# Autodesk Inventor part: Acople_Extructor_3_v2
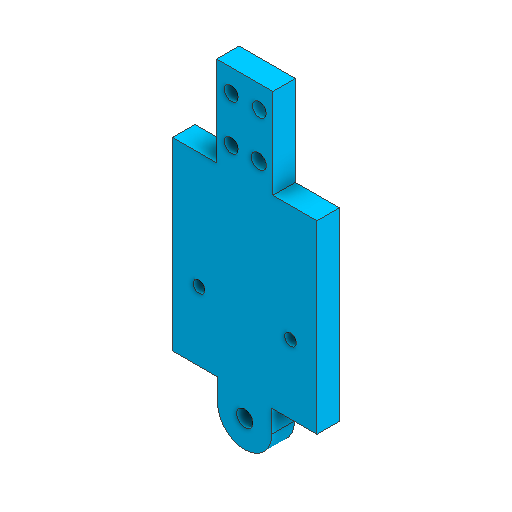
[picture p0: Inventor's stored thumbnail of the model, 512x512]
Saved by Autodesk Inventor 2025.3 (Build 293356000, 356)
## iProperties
Created: 2025-11
Part Number: Acople_Extructor_3_v2
Material: Plástico SAN
Document SubType Name: Modeling
Designer: Dell
Density: 1.068 g/cm^3
Appearance: Valor por defecto
Mass: 69.8287 g
Surface Area: 184.87 cm^2
Volume: 65.3827 cm^3
Author: Dell
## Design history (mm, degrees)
sketch "Boceto1"
  geometry: L1 (-12.5, 0)-(-12.5, -40); L2 (12.5, 0)-(12.5, -40); L3 (12.5, -40)-(-12.5, -40); L4 (-12.5, 0)-(12.5, 0); C1 r 3.1 at (6.5, -10); C2 r 3.1 at (-6, -10); C3 r 3.1 at (6.5, -30); C4 r 3.1 at (-6, -30); 1 further point
  constraints: 8 end point, 4 centre point, 2 vertical, 1 horizontal, 1 perpendicular
  dimensions: "d0" = 25 distance of L1.start L2.start; "d1" = 40 distance of L1.start L1.end; "d4" = 6.2 diameter of C1; "d6" = 6.2 diameter of C2; "d8" = 6.2 diameter of C3; "d9" = 6.2 diameter of C4
node "Plano de trabajo1"
sketch "Boceto2"
  geometry: L1 (-19.6, 0)-(44.6, 0); L2 (-19.6, 0)-(-19.6, 10); L3 (-19.6, 10)-(44.6, 10); L4 (44.6, 10)-(44.6, 0); 1 further point
  constraints: 8 end point, 2 perpendicular, 1 horizontal, 1 midpoint, 1 vertical
  dimensions: "d20" = 64.2 distance of L1.start L1.end; "d21" = 10 distance of L1.start L2.end
extrude "Extrusión2" join sketch "Boceto2" distance "d22" = 104.2; taper "d23" = 0 deg
node "Plano de trabajo2"
sketch "Boceto3" dims "d98" = 5.5
  geometry: L1 (12.5, -40)-(32.1, -40) reference; L2 (32.1, -40)-(20.35, -40); L3 (-32.1, -40)-(-12.5, -40) reference; L4 (0, -60)-(0, -132.1); L5 (-32.1, -40)-(-32.1, -144.2) reference; L6 (-32.1, -102.2)-(-32.1, -144.2); L7 (-32.1, -144.2)-(0, -144.2); L8 (32.1, -144.2)-(32.1, -102.2); L9 (32.1, -40)-(32.1, -144.2) reference; L10 (0, -144.2)-(32.1, -144.2); L11 (12.5, -40)-(12.5, 0) reference; L12 (-32.1, -57.5)-(-32.1, -53); L13 (6.441, -122.2)-(32.1, -122.2); L14 (6.441, -122.2)-(-32.1, -122.2); L15 (12.1, -132.1)-(12.1, -122.2); L16 (-12.1, -132.1)-(-12.1, -122.2); L17 (-22.3, -40)-(-22.3, -60); L18 (-22.3, -60)-(32.1, -60); L19 (-21.522, -60)-(-22.3, -60); L20 (-32.1, -60)-(-22.3, -60); L21 (-26, -40)-(-26, -67.5); L22 (-27.6, -67.5)-(-32.1, -67.5); L23 (-20.35, -60)-(-20.35, -91.6); L24 (-20.35, -91.6)-(-32.1, -91.6); L25 (20.35, -91.6)-(20.35, -60); L26 (20.35, -91.6)-(32.1, -91.6); L27 (1.4, -94.7)-(1.4, -60); L28 (1.4, -94.7)-(32.1, -94.7); L29 (18.6, -113.7)-(32.1, -113.7); L30 (18.6, -113.7)-(18.6, -60); L31 (-11.1, -60)-(-11.1, -54); L32 (-11.1, -56.75)-(-32.1, -56.75); L33 (-24.4, -66.5)-(-24.4, -67.5); L34 (-27.6, -66.5)-(-27.6, -67.5); L35 (5.9, -66.5)-(5.9, -67.5); L36 (2.7, -66.5)-(2.7, -67.5); C1 r 3.6 at (0, -132.1); C2 r 2.6 at (20.35, -91.6); C3 r 2.6 at (-20.35, -91.6); C4 r 1.6 at (18.6, -113.7); C5 r 1.6 at (1.4, -94.7); A1 r 12.1 centre (0, -132.1) between (-12.1, -132.1) and (12.1, -132.1); A2 r 1.6 centre (-26, -67.5) between (-27.6, -67.5) and (-24.4, -67.5); A3 r 1.6 centre (4.3, -67.5) between (2.7, -67.5) and (5.9, -67.5); A4 r 1.6 centre (-26, -66.5) between (-24.4, -66.5) and (-27.6, -66.5); A5 r 1.6 centre (4.3, -66.5) between (5.9, -66.5) and (2.7, -66.5); 5 further points
  constraints: 62 end point, 20 point on line, 13 perpendicular, 11 point on circle, 10 centre point, 8 tangent, 4 collinear, 4 horizontal, 3 vertical, 2 coincident, 1 midpoint, 1 vertical alignment, 9 other
  dimensions: "d37" = 72.1 distance of L4.start L4.end; "d38" = 7.2 diameter of C1; "d39" = 24.2 diameter of A1; "d68" = 5.2 diameter of C2; "d69" = 5.2 diameter of C3; "d85" = 3.2 diameter of A2; "d88" = 3.2 diameter of C4; "d90" = 3.2 diameter of C5; "d101" = 27.5 distance of L21.start L21.end; "d102" = 4.5 distance of L22.start L22.end; "d106" = 3.2 diameter of A3; "d107" = 31.6 distance of L23.start L23.end; "d108" = 11.75 distance of L23.end L24.end; "d109" = 31.6 distance of L25.start L25.end; "d110" = 11.75 distance of L25.start L26.end; "d111" = 34.7 distance of L27.start L27.end; "d112" = 30.7 distance of L27.start L28.end; "d113" = 53.7 distance of L29.start L30.end; "d114" = 13.5 distance of L29.start L29.end; "d115" = 6 distance of L31.start L31.end; "d116" = 3.2 diameter of A4; "d117" = 3.2 diameter of A5
extrude "Extrusión3" cut sketch "Boceto3" distance "d40" = 10; taper "d41" = 0 deg
extrude "Extrusión8" join sketch "Boceto1" distance "d125" = 10; taper "d126" = 0 deg
sketch "Boceto8"
  geometry: L1 (12.5, 132.1)-(-12.5, 132.1) reference; L2 (12.5, 132.1)-(6.5, 132.1); 5 further points
  constraints: 2 end point, 1 point on line
hole "Agujero2" sketch "Boceto8" at (6.5, 122.1), (-6, 122.1), (-6, 102.1), (6.5, 102.1) diameter "d131" = 6.2; stored, may be unused: countersink angle "d135" = 90 deg, drill point angle "d137" = 118 deg; dims "d132" = 6, "d133" = 4, "d134" = 2, "d136" = 10
sketch "Boceto9"
  geometry: 1 further point
hole "Agujero3" sketch "Boceto9" at (6.16, 102.103) diameter "d138" = 6.6; stored, may be unused: countersink angle "d142" = 90 deg, drill point angle "d144" = 0 deg; dims "d139" = 6, "d140" = 4, "d141" = 2, "d143" = 8
node "Sólido1"
